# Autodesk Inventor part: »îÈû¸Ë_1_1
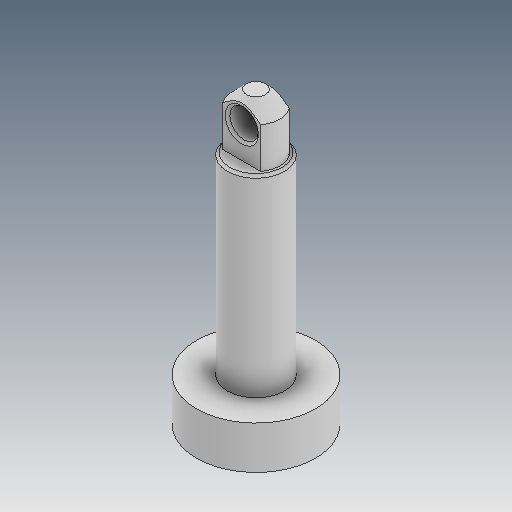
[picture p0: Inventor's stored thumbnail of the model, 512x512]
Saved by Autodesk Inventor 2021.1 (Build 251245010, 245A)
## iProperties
Created: 2019-04
Part Number: »îÈû¸Ë_1_1
Material: Ogólny
Document SubType Name: Modeling
Designer: user
Density: 1 g/cm^3
Appearance: Domyślna
Author: user
Revision Number: ÈÎºÎ
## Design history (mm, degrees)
feature "ÊäÈë1"
node "Bryła1"
